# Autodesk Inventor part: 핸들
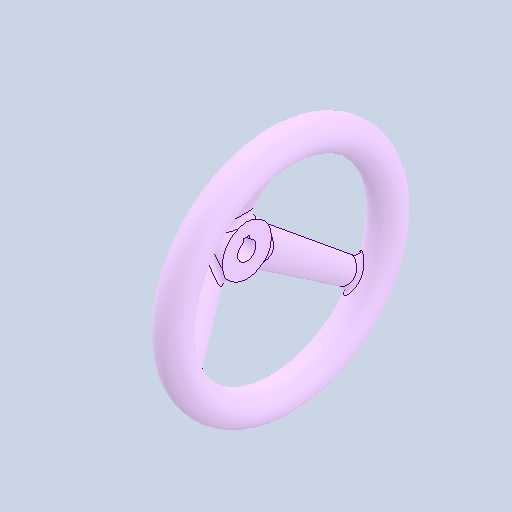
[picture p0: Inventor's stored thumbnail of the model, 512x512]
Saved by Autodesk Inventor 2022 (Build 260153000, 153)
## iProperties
Created: 2024-07
Part Number: 핸들
Material: 강철, 연강
Document SubType Name: Modeling
Designer: PC-01
Density: 7.85 g/cm^3
Appearance: 기본값
Author: jhkim
Sending System: Autodesk Inventor 2025
Preprocessor: ST-DEVELOPER v20
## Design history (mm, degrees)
feature "솔리드1"
node "솔리드2"
